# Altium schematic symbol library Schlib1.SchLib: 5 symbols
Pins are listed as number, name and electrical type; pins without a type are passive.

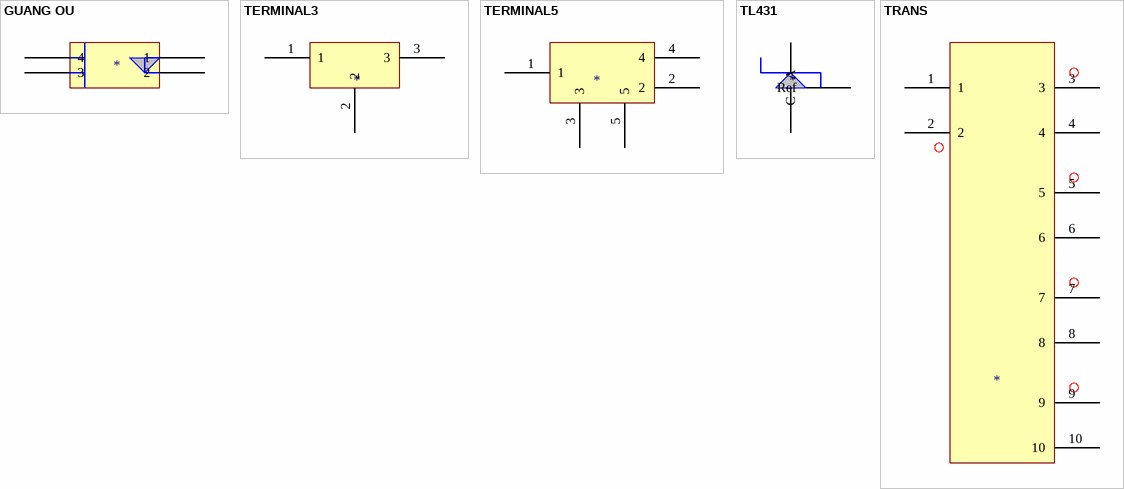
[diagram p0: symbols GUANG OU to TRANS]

## GUANG OU
designator *
pins: 1, 2, 3, 4

## TERMINAL3
designator *
pins: 1, 2, 3

## TERMINAL5
designator *
pins: 1, 2, 3, 4, 5

## TL431
designator *
pins: 1 Ref, 2 A, 3 C

## TRANS
designator *
pins: 1, 2, 3, 4, 5, 6, 7, 8, 9, 10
